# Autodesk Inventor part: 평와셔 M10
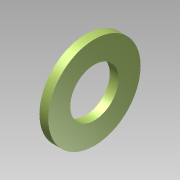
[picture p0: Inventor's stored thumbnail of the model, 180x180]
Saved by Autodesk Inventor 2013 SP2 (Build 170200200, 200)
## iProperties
Created: 2025-04
Part Number: 평와셔 M10
Material: Generic
Document SubType Name: Modeling
Designer: i
Density: 1 g/cm^3
Author: i
변환 표준: STEP AP214IS
전처리기: Build: 200, Release: 2013 SP2 Update 6 - Date: Thu 07/17/2014
전송 단위: 밀리미터
불확실성: 0.01
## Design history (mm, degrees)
node "평와셔 M101"
body "Solid1"
node "기준1"
